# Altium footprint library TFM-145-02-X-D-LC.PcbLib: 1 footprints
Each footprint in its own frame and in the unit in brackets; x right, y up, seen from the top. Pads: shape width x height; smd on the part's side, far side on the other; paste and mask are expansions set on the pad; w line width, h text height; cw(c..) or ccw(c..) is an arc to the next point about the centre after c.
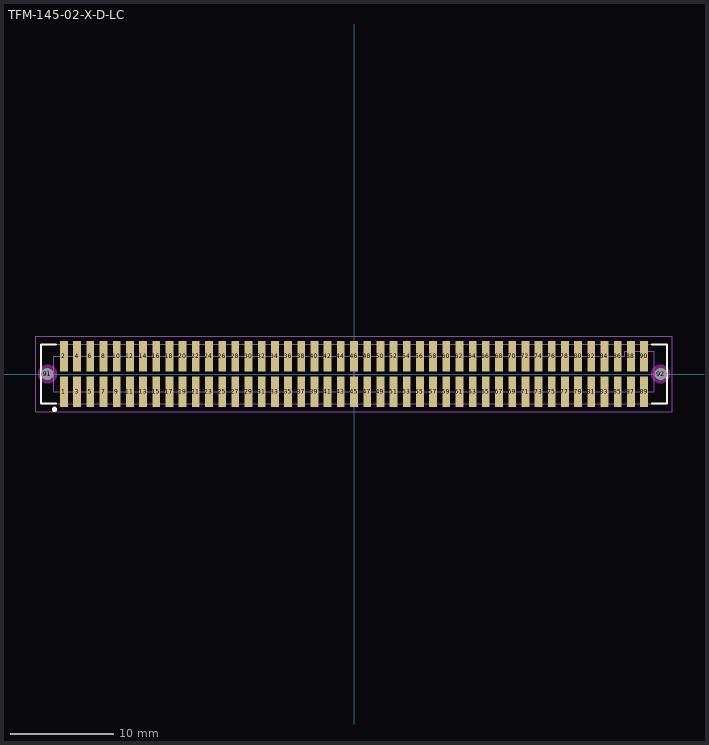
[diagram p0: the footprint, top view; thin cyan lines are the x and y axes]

## TFM-145-02-X-D-LC [mm] "1.27mm pitch, 90 pin, terminal strip; w/locking clips, SMT"
height 5.72
pads (92):
  rect 0.75x2.9 smd mask+0: 1(-27.94,-1.714) 2(-27.94,1.714) 3(-26.67,-1.714) 4(-26.67,1.714) 5(-25.4,-1.714) 6(-25.4,1.714) 7(-24.13,-1.714) 8(-24.13,1.714) 9(-22.86,-1.714) 10(-22.86,1.714) 11(-21.59,-1.714) 12(-21.59,1.714) 13(-20.32,-1.714) 14(-20.32,1.714) 15(-19.05,-1.714) 16(-19.05,1.714) 17(-17.78,-1.714) 18(-17.78,1.714) 19(-16.51,-1.714) 20(-16.51,1.714) 21(-15.24,-1.714) 22(-15.24,1.714) 23(-13.97,-1.714) 24(-13.97,1.714) 25(-12.7,-1.714) 26(-12.7,1.714) 27(-11.43,-1.714) 28(-11.43,1.714) 29(-10.16,-1.714) 30(-10.16,1.714) 31(-8.89,-1.714) 32(-8.89,1.714) 33(-7.62,-1.714) 34(-7.62,1.714) 35(-6.35,-1.714) 36(-6.35,1.714) 37(-5.08,-1.714) 38(-5.08,1.714) 39(-3.81,-1.714) 40(-3.81,1.714) 41(-2.54,-1.714) 42(-2.54,1.714) 43(-1.27,-1.714) 44(-1.27,1.714) 45(0,-1.714) 46(0,1.714) 47(1.27,-1.714) 48(1.27,1.714) 49(2.54,-1.714) 50(2.54,1.714) 51(3.81,-1.714) 52(3.81,1.714) 53(5.08,-1.714) 54(5.08,1.714) 55(6.35,-1.714) 56(6.35,1.714) 57(7.62,-1.714) 58(7.62,1.714) 59(8.89,-1.714) 60(8.89,1.714) 61(10.16,-1.714) 62(10.16,1.714) 63(11.43,-1.714) 64(11.43,1.714) 65(12.7,-1.714) 66(12.7,1.714) 67(13.97,-1.714) 68(13.97,1.714) 69(15.24,-1.714) 70(15.24,1.714) 71(16.51,-1.714) 72(16.51,1.714) 73(17.78,-1.714) 74(17.78,1.714) 75(19.05,-1.714) 76(19.05,1.714) 77(20.32,-1.714) 78(20.32,1.714) 79(21.59,-1.714) 80(21.59,1.714) 81(22.86,-1.714) 82(22.86,1.714) 83(24.13,-1.714) 84(24.13,1.714) 85(25.4,-1.714) 86(25.4,1.714) 87(26.67,-1.714) 88(26.67,1.714) 89(27.94,-1.714) 90(27.94,1.714)
  round 1 hole 1.2 unplated mask+0: 91(-29.527,0) 92(29.527,0)
Top Overlay:
  circle w0.25: c-28.85,-3.4 r0.125
  lines w0.2: -28.7,-2.85 -30.15,-2.85 -30.15,2.85 -28.7,2.85 ; 28.7,-2.85 30.15,-2.85 30.15,2.85 28.7,2.85
Keep-Out Layer:
  pour cut-out: -28.62,0 -28.651,0.235 -28.742,0.454 -28.886,0.642 -29.074,0.786 -29.293,0.877 -29.528,0.908 -29.763,0.877 -29.982,0.786 -30.17,0.642 -30.314,0.454 -30.405,0.235 -30.435,0 -30.405,-0.235 -30.314,-0.454 -30.17,-0.642 -29.982,-0.786 -29.763,-0.877 -29.528,-0.908 -29.293,-0.877 -29.074,-0.786 -28.886,-0.642 -28.742,-0.454 -28.651,-0.235
  pour cut-out: 30.435,0 30.405,0.235 30.314,0.454 30.17,0.642 29.982,0.786 29.763,0.877 29.528,0.908 29.293,0.877 29.074,0.786 28.886,0.642 28.742,0.454 28.651,0.235 28.62,0 28.651,-0.235 28.742,-0.454 28.886,-0.642 29.074,-0.786 29.293,-0.877 29.528,-0.908 29.763,-0.877 29.982,-0.786 30.17,-0.642 30.314,-0.454 30.405,-0.235
Mechanical 12:
  lines w0.001: -30.15,-2.85 30.15,-2.85 30.15,2.85 -30.15,2.85 -30.15,-2.85 ; -28.9,-1.7 28.9,-1.7 28.9,2.2 26.1,2.2 26.1,1.7 -28.9,1.7 -28.9,-1.7
Mechanical 13:
  circle w0.1: c-28.837,-3.379 r0.127
  lines w0.1: -30.15,-2.85 30.15,-2.85 30.15,2.85 -30.15,2.85 -30.15,-2.85 ; -28.9,-1.7 28.9,-1.7 28.9,2.2 26.1,2.2 26.1,1.7 -28.9,1.7 -28.9,-1.7
  text ".Designator" at 0,-0.127 h1.52
Mechanical 15:
  lines w0.05: -0.5,0 0.5,0 ; 0,-0.5 0,0.5 ; -30.65,-3.65 30.65,-3.65 30.65,3.65 -30.65,3.65 -30.65,-3.65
